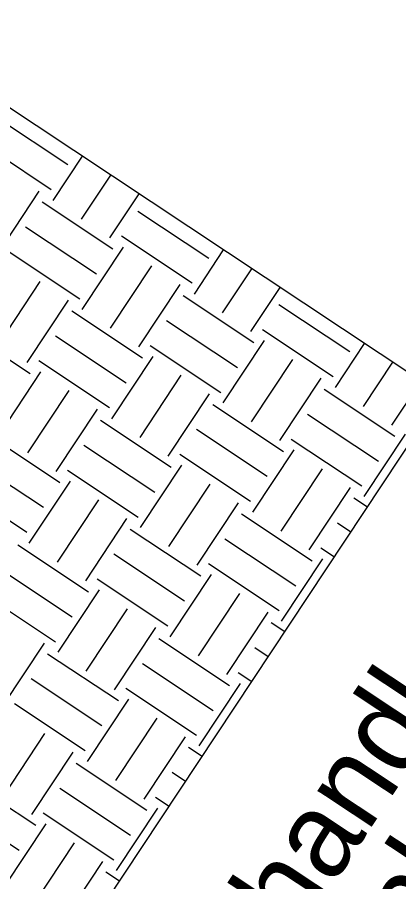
# Model space of a CAD drawing. Extents: x 561231 to 564935, y 589159 to 602519.
# Drawn here: x 564360.74 to 564378.77, y 589611.64 to 589652.5 of the extents above; entities that cross this region are included whole.
import ezdxf

# ---------------------------------------------------------------- set-up
doc = ezdxf.new("R2010")
doc.units = 0
doc.layers.add('Old_Level_1', color=7, linetype='Continuous')

msp = doc.modelspace()

# ---------------------------------------------------------------- linework, layer by layer
at = {"layer": 'Old_Level_1'}
for p, q in [((564380.81, 589634.66), (564353.925, 589652.497)), ((564359.779, 589647.763), (564363.124, 589645.543)), ((564358.997, 589646.585), (564362.343, 589644.366)), ((564362.444, 589643.842), (564363.827, 589645.928)), ((564363.782, 589642.955), (564365.165, 589645.04)), ((564359.821, 589641.341), (564361.775, 589644.286)), ((564365.12, 589642.067), (564366.503, 589644.152)), ((564361.914, 589643.77), (564365.26, 589641.55)), ((564366.446, 589643.339), (564369.791, 589641.12)), ((564361.132, 589642.592), (564364.478, 589640.372)), ((564365.664, 589642.161), (564369.01, 589639.942)), ((564360.352, 589641.413), (564363.697, 589639.194)), ((564363.812, 589638.693), (564365.765, 589641.639)), ((564369.111, 589639.419), (564370.494, 589641.504)), ((564365.15, 589637.805), (564367.104, 589640.751)), ((564370.449, 589638.531), (564371.832, 589640.616)), ((564359.875, 589637.063), (564361.829, 589640.009)), ((564366.488, 589636.918), (564368.442, 589639.863)), ((564371.787, 589637.643), (564373.17, 589639.729)), ((564368.581, 589639.347), (564371.927, 589637.127)), ((564361.213, 589636.176), (564363.167, 589639.121)), ((564373.113, 589638.916), (564376.458, 589636.697)), ((564363.321, 589638.627), (564366.666, 589636.407)), ((564367.8, 589638.168), (564371.145, 589635.949)), ((564358.007, 589637.879), (564361.353, 589635.659)), ((564372.332, 589637.738), (564375.677, 589635.519)), ((564362.539, 589637.449), (564365.884, 589635.229)), ((564367.019, 589636.99), (564370.364, 589634.771)), ((564370.479, 589634.27), (564372.433, 589637.215)), ((564375.778, 589634.996), (564377.161, 589637.081)), ((564365.204, 589633.528), (564367.157, 589636.473)), ((564361.758, 589636.27), (564365.103, 589634.051)), ((564371.817, 589633.382), (564373.771, 589636.327)), ((564377.116, 589634.108), (564378.499, 589636.193)), ((564359.905, 589632.802), (564361.859, 589635.747)), ((564366.542, 589632.64), (564368.495, 589635.586)), ((564373.156, 589632.494), (564375.109, 589635.44)), ((564378.454, 589633.22), (564379.837, 589635.305)), ((564361.244, 589631.914), (564363.197, 589634.859)), ((564375.248, 589634.923), (564378.593, 589632.704)), ((564357.588, 589599.643), (564380.81, 589634.66)), ((564367.88, 589631.752), (564369.834, 589634.698)), ((564369.988, 589634.203), (564373.333, 589631.984)), ((564362.582, 589631.026), (564364.535, 589633.972)), ((564374.467, 589633.745), (564377.812, 589631.526)), ((564364.674, 589633.455), (564368.019, 589631.236)), ((564369.206, 589633.025), (564372.551, 589630.806)), ((564377.146, 589629.846), (564379.1, 589632.792)), ((564359.413, 589632.736), (564362.759, 589630.516)), ((564373.685, 589632.567), (564377.03, 589630.348)), ((564363.893, 589632.277), (564367.238, 589630.058)), ((564371.871, 589629.105), (564373.824, 589632.05)), ((564358.632, 589631.557), (564361.977, 589629.338)), ((564368.425, 589631.847), (564371.77, 589629.627)), ((564366.572, 589628.378), (564368.526, 589631.324)), ((564373.209, 589628.217), (564375.163, 589631.163)), ((564363.111, 589631.099), (564366.456, 589628.88)), ((564357.85, 589630.379), (564361.196, 589628.16)), ((564361.297, 589627.637), (564363.25, 589630.582)), ((564367.911, 589627.491), (564369.864, 589630.436)), ((564374.547, 589627.329), (564376.501, 589630.275)), ((564362.635, 589626.749), (564364.589, 589629.695)), ((564369.249, 589626.603), (564371.202, 589629.548)), ((564376.654, 589629.78), (564377.293, 589629.356)), ((564363.973, 589625.861), (564365.927, 589628.807)), ((564371.341, 589629.032), (564374.686, 589626.813)), ((564366.08, 589628.312), (564369.425, 589626.093)), ((564375.873, 589628.602), (564376.512, 589628.178)), ((564360.767, 589627.564), (564364.112, 589625.345)), ((564370.56, 589627.854), (564373.905, 589625.635)), ((564365.299, 589627.134), (564368.644, 589624.914)), ((564375.091, 589627.424), (564375.731, 589627)), ((564369.778, 589626.676), (564373.124, 589624.456)), ((564373.239, 589623.955), (564375.193, 589626.901)), ((564359.986, 589626.386), (564363.331, 589624.167)), ((564364.518, 589625.956), (564367.863, 589623.736)), ((564367.964, 589623.214), (564369.917, 589626.159)), ((564362.666, 589622.488), (564364.619, 589625.433)), ((564359.204, 589625.208), (564362.55, 589622.988)), ((564369.302, 589622.326), (564371.256, 589625.272)), ((564364.004, 589621.6), (564365.957, 589624.545)), ((564370.64, 589621.438), (564372.594, 589624.384)), ((564372.747, 589623.889), (564373.386, 589623.465)), ((564365.342, 589620.712), (564367.295, 589623.657)), ((564367.434, 589623.141), (564370.779, 589620.922)), ((564360.066, 589619.97), (564362.02, 589622.916)), ((564371.966, 589622.711), (564372.605, 589622.287)), ((564362.173, 589622.421), (564365.519, 589620.201)), ((564366.653, 589621.963), (564369.998, 589619.743)), ((564371.185, 589621.532), (564371.823, 589621.109)), ((564361.392, 589621.243), (564364.737, 589619.023)), ((564369.332, 589618.064), (564371.286, 589621.01)), ((564365.872, 589620.784), (564369.217, 589618.565)), ((564364.057, 589617.322), (564366.011, 589620.268)), ((564360.611, 589620.064), (564363.956, 589617.845)), ((564365.396, 589616.435), (564367.349, 589619.38)), ((564360.096, 589615.709), (564362.05, 589618.654)), ((564366.734, 589615.547), (564368.687, 589618.493)), ((564361.434, 589614.821), (564363.388, 589617.766)), ((564368.84, 589617.998), (564369.479, 589617.574)), ((564363.527, 589617.25), (564366.872, 589615.03)), ((564358.267, 589616.53), (564361.612, 589614.31)), ((564368.059, 589616.819), (564368.698, 589616.396)), ((564362.746, 589616.072), (564366.091, 589613.852)), ((564367.278, 589615.641), (564367.917, 589615.217)), ((564357.485, 589615.351), (564360.83, 589613.132)), ((564361.964, 589614.893), (564365.309, 589612.674)), ((564365.426, 589612.173), (564367.379, 589615.119)), ((564360.15, 589611.431), (564362.104, 589614.377)), ((564361.488, 589610.543), (564363.442, 589613.489)), ((564362.826, 589609.656), (564364.78, 589612.601)), ((564364.933, 589612.106), (564365.573, 589611.683))]:
    msp.add_line(p, q, dxfattribs=at)

# ---------------------------------------------------------------- texts
for s, p in [(' toward planter, firming ', (564369.222, 589592.424)), ('4. Pull handle of bar ', (564364.92, 589595.276)), (' soil at bottom.', (564373.523, 589589.571))]:
    msp.add_text(s, height=4.01452, rotation=56.4482, dxfattribs=at).set_placement(p)

doc.saveas('drawing.dxf')
